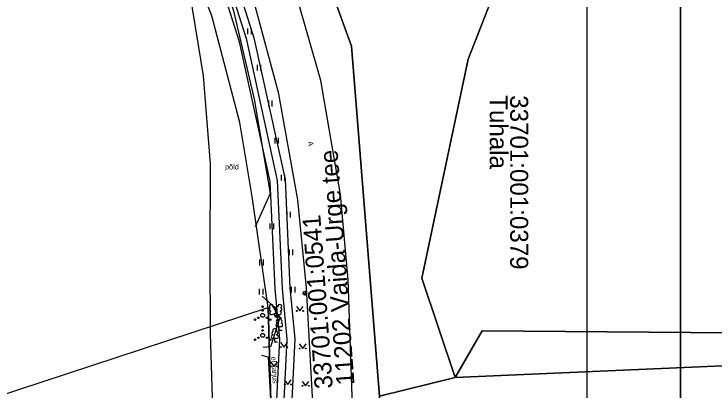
# Model space of a CAD drawing. Extents: x 554947 to 555436, y 6564938 to 6565792.
# Drawn here: x 555146.4 to 555239.7, y 6565295.3 to 6565345.5 of the extents above; entities that cross this region are included whole.
import ezdxf

# ---------------------------------------------------------------- set-up
doc = ezdxf.new("R2010")
doc.units = 0
for name, color, linetype in [('AED', 7, 'Continuous'), ('HALJASTUS', 7, 'Continuous'), ('KASUTUSALA', 7, 'Continuous'), ('KPKAABEL', 7, 'Continuous'), ('PIIR', 7, 'Continuous'), ('POST', 7, 'Continuous'), ('PR_SIDE', 7, 'Continuous'), ('PUU', 7, 'Continuous'), ('TEE', 7, 'Continuous'), ('VORMISTUS_1', 7, 'Continuous')]:
    doc.layers.add(name, color=color, linetype=linetype)

msp = doc.modelspace()

# ---------------------------------------------------------------- linework, layer by layer
at = {"layer": 'AED'}
msp.add_lwpolyline([(555179.37, 6565300.078), (555180.242, 6565299.846), (555180.75, 6565290.874), (555180.137, 6565280.616), (555178.982, 6565264.788), (555177.984, 6565255.288), (555177.306, 6565249.05), (555173.486, 6565227.422), (555169.733, 6565212.423), (555163.779, 6565189.534), (555156.086, 6565161.758), (555151.428, 6565143.905), (555146.995, 6565125.891), (555142.273, 6565107.514), (555136.767, 6565086.759), (555131.214, 6565064.984), (555128.386, 6565056.617), (555127.142, 6565056.522)], dxfattribs=at)
at = {"layer": 'HALJASTUS'}
for p, q in [((555177.507, 6565343.535), (555177.507, 6565342.774)), ((555177.962, 6565343.535), (555177.962, 6565342.774)), ((555178.792, 6565338.704), (555178.792, 6565337.943)), ((555179.247, 6565338.704), (555179.247, 6565337.943)), ((555180.298, 6565333.939), (555180.298, 6565333.178)), ((555180.753, 6565333.939), (555180.753, 6565333.178)), ((555181.143, 6565329.011), (555181.143, 6565328.25)), ((555181.598, 6565329.011), (555181.598, 6565328.25)), ((555181.988, 6565324.083), (555181.988, 6565323.322)), ((555182.443, 6565324.083), (555182.443, 6565323.322)), ((555182.744, 6565319.144), (555182.744, 6565318.383)), ((555183.199, 6565319.144), (555183.199, 6565318.383)), ((555180.486, 6565317.59), (555180.486, 6565316.829)), ((555180.941, 6565317.59), (555180.941, 6565316.829)), ((555183.038, 6565314.153), (555183.038, 6565313.392)), ((555183.493, 6565314.153), (555183.493, 6565313.392)), ((555179.108, 6565312.784), (555179.108, 6565312.023)), ((555179.563, 6565312.784), (555179.563, 6565312.023)), ((555179.069, 6565308.891), (555179.069, 6565308.13)), ((555179.524, 6565308.891), (555179.524, 6565308.13)), ((555183.331, 6565309.162), (555183.331, 6565308.401)), ((555183.786, 6565309.162), (555183.786, 6565308.401)), ((555184.008, 6565306.559), (555184.471, 6565305.953)), ((555184.471, 6565305.953), (555184.917, 6565306.559)), ((555181.901, 6565301.748), (555182.364, 6565301.141)), ((555182.364, 6565301.141), (555182.81, 6565301.748)), ((555184.386, 6565301.574), (555184.85, 6565300.967)), ((555184.85, 6565300.967), (555185.295, 6565301.574)), ((555180.571, 6565299.18), (555181.034, 6565298.573)), ((555181.034, 6565298.573), (555181.48, 6565299.18)), ((555182.395, 6565296.772), (555182.858, 6565296.166)), ((555182.858, 6565296.166), (555183.304, 6565296.772)), ((555184.765, 6565296.588), (555185.228, 6565295.981)), ((555185.228, 6565295.981), (555185.674, 6565296.588))]:
    msp.add_line(p, q, dxfattribs=at)
for points in [[(555147.437, 6565403.198), (555151.813, 6565400.39), (555156.402, 6565394.192), (555163.761, 6565377.834), (555172.39, 6565356.6), (555175.608, 6565345.88), (555178.387, 6565334.156), (555180.524, 6565321.581), (555178.521, 6565317.128)], [(555179.431, 6565307.904), (555180.696, 6565306.825), (555181.786, 6565305.035), (555180.57, 6565301.175), (555179.588, 6565301.089)]]:
    msp.add_lwpolyline(points, dxfattribs=at)
for centre, radius in [((555179.511, 6565306.513), 0.1), ((555179.511, 6565305.363), 0.25), ((555179.511, 6565306.013), 0.1), ((555184.07, 6565305.953), 0.055), ((555184.899, 6565305.953), 0.055), ((555178.511, 6565304.788), 0.1), ((555178.946, 6565305.038), 0.1), ((555180.076, 6565305.038), 0.1), ((555180.511, 6565304.788), 0.1), ((555179.511, 6565303.857), 0.1), ((555179.511, 6565302.707), 0.25), ((555179.511, 6565303.357), 0.1), ((555178.511, 6565302.132), 0.1), ((555178.946, 6565302.382), 0.1), ((555180.076, 6565302.382), 0.1), ((555180.511, 6565302.132), 0.1), ((555181.963, 6565301.141), 0.055), ((555182.792, 6565301.141), 0.055), ((555184.449, 6565300.967), 0.055), ((555185.277, 6565300.967), 0.055), ((555180.633, 6565298.573), 0.055), ((555181.462, 6565298.573), 0.055), ((555182.457, 6565296.166), 0.055), ((555183.286, 6565296.166), 0.055), ((555184.827, 6565295.981), 0.055), ((555185.656, 6565295.981), 0.055)]:
    msp.add_circle(centre, radius, dxfattribs=at)
at = {"layer": 'KASUTUSALA'}
for points in [[(555129.194, 6565453.133), (555137.609, 6565433.851), (555144.751, 6565418.945), (555157.258, 6565394.612), (555165.015, 6565377.641), (555173.731, 6565356.879), (555178.352, 6565342.28), (555182.507, 6565323.462), (555183.157, 6565309.022), (555183.79, 6565302.23), (555182.806, 6565282.402), (555182.407, 6565269.888), (555181.762, 6565260.751), (555194.028, 6565259.888), (555193.816, 6565257.898), (555181.976, 6565258.731), (555181.603, 6565258.495), (555181.453, 6565256.368), (555178.899, 6565239.742)], [(555176.937, 6565240.135), (555179.22, 6565254.85), (555179.244, 6565255.16), (555179.541, 6565258.936), (555179.592, 6565259.587), (555180.41, 6565269.99), (555180.41, 6565269.99), (555180.41, 6565269.99), (555180.588, 6565278.069), (555181.785, 6565302.187), (555181.161, 6565308.884), (555180.517, 6565323.199), (555176.418, 6565341.761), (555171.852, 6565356.189), (555163.184, 6565376.838), (555155.458, 6565393.739), (555142.959, 6565418.055), (555135.79, 6565433.019), (555127.369, 6565452.314)]]:
    msp.add_lwpolyline(points, dxfattribs=at)
at = {"layer": 'KPKAABEL'}
msp.add_lwpolyline([(555126.894, 6565446.731), (555132.737, 6565435.388), (555136.366, 6565427.872), (555142.195, 6565415.637), (555145.001, 6565409.613), (555146.957, 6565405.365), (555152.799, 6565392.474), (555157.576, 6565380.671), (555161.529, 6565371.444), (555166.139, 6565359.889), (555169.783, 6565348.422), (555171.572, 6565337.25), (555172.523, 6565325.522), (555172.476, 6565313.268), (555172.511, 6565302.969), (555172.901, 6565290.135), (555172.887, 6565279.431), (555172.817, 6565266.938), (555172.536, 6565254.014), (555171.281, 6565241.464)], dxfattribs=at)
at = {"layer": 'PIIR'}
for points in [[(555393.069, 6565560.972), (555353.12, 6565523.87), (555343.14, 6565512.46), (555302.6, 6565539.71), (555242.37, 6565583.94), (555179.42, 6565586.32), (555138.98, 6565580.6), (555121.18, 6565602.26), (555116.17, 6565610.5), (555109.96, 6565624.83), (555093.56, 6565628.47), (555079.04, 6565618.4), (555074.13, 6565607.82), (555075.34, 6565593.24), (555091.74, 6565551.94), (555171.91, 6565394.64), (555191.35, 6565341.19), (555195.08, 6565294.61), (555195.28, 6565271.63), (555191.64, 6565237.48)], [(555153.01, 6565448.47), (555207.22, 6565406.57), (555216.83, 6565392.35), (555221.23, 6565376.06), (555206.9, 6565339.44), (555200.72, 6565310.3), (555205.15, 6565297.11), (555195.08, 6565294.61), (555191.35, 6565341.19), (555171.91, 6565394.64), (555091.74, 6565551.94)], [(555176.93, 6565240.09), (555179.22, 6565254.85), (555180.41, 6565269.99), (555180.8, 6565287.7), (555180.26, 6565306.43), (555178.11, 6565321.18), (555176.49, 6565331.05), (555172.72, 6565345.23), (555166.64, 6565360.5), (555160.07, 6565375.54), (555144.16, 6565410.6), (555124.27, 6565454.45)], [(555307.598, 6565160.101), (555289.11, 6565186.6), (555261.42, 6565218.27), (555255.75, 6565226.79), (555254.61, 6565228.5), (555256.63, 6565245.54), (555293.54, 6565286.23), (555292.52, 6565297.57), (555275.38, 6565300.17), (555205.15, 6565297.11), (555208.78, 6565303.3), (555303.13, 6565302.54), (555320.51, 6565314.61), (555338.117, 6565285.943)], [(555191.64, 6565237.48), (555195.28, 6565271.63), (555195.08, 6565294.61), (555205.15, 6565297.11), (555275.38, 6565300.17), (555292.52, 6565297.57), (555293.54, 6565286.23), (555256.63, 6565245.54)]]:
    msp.add_lwpolyline(points, dxfattribs=at)
for points in [[(555153.01, 6565448.47), (555161.15, 6565451.45), (555173.66, 6565456.03), (555207.29, 6565506.14), (555287.77, 6565518.56), (555302.6, 6565539.71), (555343.14, 6565512.46), (555319.44, 6565481.04), (555323.07, 6565461.26), (555312.9, 6565433.84), (555316.84, 6565372.52), (555318.72, 6565342.57), (555320.51, 6565314.61), (555303.13, 6565302.54), (555208.78, 6565303.3), (555205.15, 6565297.11), (555200.72, 6565310.3), (555206.9, 6565339.44), (555221.23, 6565376.06), (555216.83, 6565392.35), (555207.22, 6565406.57)], [(554962.55, 6565234.93), (555180.26, 6565306.43), (555180.8, 6565287.7), (555180.41, 6565269.99), (555179.22, 6565254.85), (555176.93, 6565240.09), (555172.7, 6565220.76), (555117.14, 6565008.97), (555108.27, 6564991.27)]]:
    msp.add_lwpolyline(points, close=True, dxfattribs=at)
at = {"layer": 'POST'}
msp.add_line((555184.97, 6565308.147), (555185.323, 6565308.5), dxfattribs=at)
msp.add_circle((555185.147, 6565308.323), 0.25, dxfattribs=at)
for radius, start, end in [(0.225, 224.85406, 45.03563), (0.2, 224.84272, 45.04698), (0.175, 224.82813, 45.06157), (0.15, 224.80867, 45.08103), (0.125, 224.78144, 45.10826), (0.1, 224.74058, 45.14911), (0.075, 224.67249, 45.2172), (0.05, 224.53632, 45.35338), (0.025, 224.12776, 45.76193)]:
    msp.add_arc((555185.147, 6565308.323), radius, start, end, dxfattribs=at)
at = {"layer": 'PR_SIDE'}
msp.add_lwpolyline([(555177.913, 6565239.906), (555180.459, 6565256.479), (555181.409, 6565269.94), (555181.807, 6565282.443), (555182.788, 6565302.209), (555182.159, 6565308.954), (555181.512, 6565323.331), (555177.385, 6565342.021), (555172.792, 6565356.535), (555164.1, 6565377.24), (555156.359, 6565394.176), (555143.855, 6565418.501), (555136.7, 6565433.435), (555128.282, 6565452.724)], dxfattribs=at)
at = {"layer": 'PUU'}
for p, q in [((555180.785, 6565305.477), (555181.23, 6565305.652)), ((555181.225, 6565305.142), (555181.05, 6565305.582)), ((555181.225, 6565305.142), (555181.405, 6565305.582)), ((555181.23, 6565305.652), (555181.67, 6565305.472)), ((555181.605, 6565305.142), (555181.225, 6565305.142)), ((555181.963, 6565303.841), (555181.483, 6565303.841)), ((555181.723, 6565303.366), (555181.723, 6565303.841)), ((555182.103, 6565303.366), (555181.723, 6565303.366)), ((555181.369, 6565302.282), (555180.889, 6565302.282)), ((555181.129, 6565301.807), (555181.129, 6565302.282)), ((555181.509, 6565301.807), (555181.129, 6565301.807))]:
    msp.add_line(p, q, dxfattribs=at)
msp.add_lwpolyline([(555181.23, 6565306.147), (555181.21, 6565306.072), (555181.21, 6565306.052), (555181.22, 6565306.022), (555181.24, 6565305.987), (555181.245, 6565305.967), (555181.23, 6565305.932), (555181.205, 6565305.882), (555181.2, 6565305.857), (555181.205, 6565305.842), (555181.215, 6565305.812), (555181.25, 6565305.752), (555181.255, 6565305.732), (555181.25, 6565305.712), (555181.235, 6565305.677), (555181.23, 6565305.652)], dxfattribs=at)
for centre, radius, start, end in [((555180.668, 6565306.556), 0.256, 111.50269, 232.51731), ((555180.668, 6565306.556), 0.256, 350.48556, 111.50017), ((555181.002, 6565306.306), 0.224, 308.50412, 111.57247), ((555181.466, 6565306.301), 0.225, 67.7016, 230.51262), ((555181.804, 6565306.547), 0.256, 67.6168, 188.63142), ((555181.804, 6565306.547), 0.256, 306.59966, 67.61428), ((555180.594, 6565306.145), 0.224, 111.43041, 274.49868), ((555180.699, 6565305.7), 0.237, 111.50143, 291.50036), ((555181.229, 6565305.909), 0.237, 66.76552, 111.50149), ((555181.76, 6565305.692), 0.237, 247.61661, 67.61554), ((555181.871, 6565306.135), 0.224, 264.6183, 67.68657), ((555181.553, 6565304.539), 0.233, 109.02174, 253.14154), ((555181.723, 6565304.886), 0.277, 332.5799, 207.4201), ((555181.893, 6565304.539), 0.233, 286.85082, 70.98591), ((555181.486, 6565304.079), 0.238, 90.0016, 269.3953), ((555181.961, 6565304.079), 0.238, 270.6047, 89.9984), ((555180.959, 6565302.98), 0.233, 109.02174, 253.14154), ((555181.129, 6565303.327), 0.277, 332.5799, 207.4201), ((555181.299, 6565302.98), 0.233, 286.85082, 70.98591), ((555180.892, 6565302.52), 0.238, 90.0016, 269.3953), ((555181.367, 6565302.52), 0.238, 270.6047, 89.9984)]:
    msp.add_arc(centre, radius, start, end, dxfattribs=at)
at = {"layer": 'TEE'}
for points in [[(555190.709, 6565248.513), (555189.563, 6565248.443), (555190.146, 6565254.361), (555191.039, 6565262.566), (555191.617, 6565272.16), (555191.671, 6565280.957), (555191.452, 6565294.595), (555190.904, 6565310.102), (555189.89, 6565321.445), (555187.257, 6565336.603), (555183.958, 6565348.1), (555179.78, 6565359.387), (555170.643, 6565380.205), (555162.823, 6565397.349), (555156.491, 6565411.721), (555150.933, 6565424.006), (555146.697, 6565433.416), (555136.695, 6565455.531)], [(555131.266, 6565453.894), (555141.635, 6565431.431), (555145.957, 6565421.634), (555151.76, 6565408.809), (555158.151, 6565395.066), (555165.93, 6565378.047), (555174.733, 6565357.312), (555178.536, 6565346.409), (555181.58, 6565335.07), (555184.177, 6565320.727), (555185.301, 6565309.018), (555186.111, 6565294.522), (555186.299, 6565280.132), (555185.431, 6565263.333), (555184.399, 6565254.7), (555183.594, 6565248.995), (555179.697, 6565227.862)]]:
    msp.add_lwpolyline(points, dxfattribs=at)
at = {"layer": 'VORMISTUS_1'}
for points in [[(555045.188, 6565158.913), (555235.188, 6565158.913), (555235.188, 6565433.913), (555045.188, 6565433.913)], [(555045.188, 6565433.913), (555235.188, 6565433.913), (555235.188, 6565158.913), (555045.188, 6565158.913)], [(555222.688, 6565184.913), (555057.688, 6565184.913), (555057.688, 6565394.913), (555222.688, 6565394.913)]]:
    msp.add_lwpolyline(points, close=True, dxfattribs=at)

# ---------------------------------------------------------------- texts
at = {"layer": 'AED'}
msp.add_text('el karjus', height=0.7, rotation=273.19709, dxfattribs=at).set_placement((555180.661, 6565299.869))
at = {"layer": 'HALJASTUS'}
msp.add_text('põld', height=0.7, rotation=359.95437, dxfattribs=at).set_placement((555174.5, 6565324.781))
at = {"layer": 'PIIR'}
for s, rotation, p in [('Tuhala', 270, (555209.772, 6565334.663)), ('33701:001:0379', 270, (555212.495, 6565334.663)), ('11202 Vaida-Urge tee', 94.14867, (555191.757, 6565296.15)), ('33701:001:0541', 94.14867, (555188.866, 6565295.685))]:
    msp.add_text(s, height=2.4, rotation=rotation, dxfattribs=at).set_placement(p)
at = {"layer": 'TEE'}
msp.add_text('A', height=0.7, rotation=278.19181, dxfattribs=at).set_placement((555185.531, 6565328.477))

doc.saveas('drawing.dxf')
